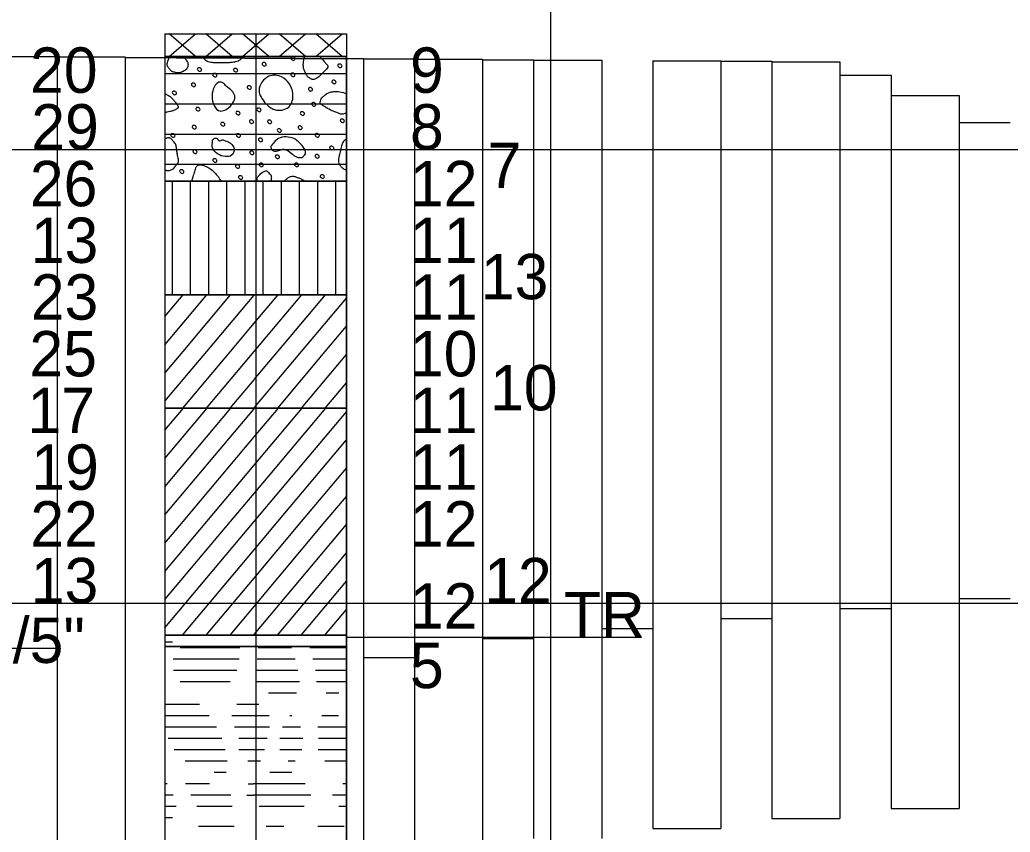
# Model space of a CAD drawing. Extents: x -2280229 to 1306, y -58886 to 440.
# Drawn here: x 461.59 to 505.23, y 72.12 to 107.93 of the extents above; entities that cross this region are included whole.
import ezdxf

# ---------------------------------------------------------------- set-up
doc = ezdxf.new("R2010")
doc.units = 0
for name, color, linetype in [('BR_P_Sub_Deep_Object', 7, 'Continuous'), ('GT_Project_Soil_Layers', 7, 'Continuous'), ('SC_Scratch2', 7, 'Continuous'), ('SC_Scratch3', 7, 'Continuous'), ('SH_Minor_Grid_Line', 7, 'Continuous')]:
    doc.layers.add(name, color=color, linetype=linetype)

msp = doc.modelspace()

# ---------------------------------------------------------------- linework, layer by layer
at = {"layer": 'BR_P_Sub_Deep_Object'}
for p, q in [((463.234, 106.302), (463.234, 70.968)), ((466.234, 106.287), (466.234, 70.968)), ((466.234, 106.268), (468.484, 106.268)), ((468.484, 106.254), (471.484, 106.254)), ((471.484, 106.234), (473.734, 106.234)), ((473.734, 106.22), (476.734, 106.22)), ((476.734, 106.22), (476.734, 70.824)), ((476.734, 106.201), (478.984, 106.201)), ((478.984, 106.201), (478.984, 71.405)), ((481.984, 106.186), (481.984, 71.405)), ((484.234, 106.167), (484.234, 71.844)), ((487.234, 106.153), (487.234, 71.844)), ((489.484, 106.134), (489.484, 72.283)), ((489.484, 106.119), (492.484, 106.119)), ((492.484, 106.119), (492.484, 72.283)), ((492.484, 106.1), (494.734, 106.1)), ((494.734, 106.1), (494.734, 72.722)), ((494.734, 106.076), (497.734, 106.076)), ((497.734, 106.076), (497.734, 72.722)), ((497.734, 105.481), (499.984, 105.481)), ((499.984, 105.481), (499.984, 73.161)), ((499.984, 104.588), (502.984, 104.588)), ((502.984, 104.588), (502.984, 73.161)), ((502.984, 103.398), (505.234, 103.398)), ((502.984, 82.412), (505.234, 82.412)), ((497.734, 81.973), (499.984, 81.973)), ((492.484, 81.534), (494.734, 81.534)), ((487.234, 81.095), (489.484, 81.095)), ((481.984, 80.656), (484.234, 80.656)), ((463.234, 80.221), (460.984, 80.221)), ((476.734, 79.824), (478.984, 79.824)), ((499.984, 73.161), (502.984, 73.161)), ((494.734, 72.722), (497.734, 72.722)), ((489.484, 72.283), (492.484, 72.283))]:
    msp.add_line(p, q, dxfattribs=at)
at = {"layer": 'GT_Project_Soil_Layers'}
for p, q in [((468.172, 106.308), (469.326, 107.308)), ((469.326, 106.308), (468.172, 107.308)), ((469.788, 106.308), (470.943, 107.308)), ((470.943, 106.308), (469.788, 107.308)), ((471.405, 106.308), (472.56, 107.308)), ((472.56, 106.308), (471.405, 107.308)), ((473.021, 106.308), (474.176, 107.308)), ((474.176, 106.308), (473.021, 107.308)), ((474.638, 106.308), (475.793, 107.308)), ((475.793, 106.308), (474.638, 107.308)), ((467.982, 106.308), (467.982, 106.308)), ((467.984, 105.558), (471.913, 105.558)), ((471.916, 105.558), (475.984, 105.558)), ((467.984, 104.225), (471.913, 104.225)), ((471.916, 104.225), (475.984, 104.225)), ((467.984, 102.891), (471.913, 102.891)), ((471.916, 102.891), (475.984, 102.891)), ((467.984, 101.557), (471.913, 101.557)), ((471.916, 101.557), (475.984, 101.557)), ((468.316, 98.309), (468.316, 100.808)), ((469.116, 98.309), (469.116, 100.808)), ((469.916, 98.309), (469.916, 100.808)), ((470.716, 98.309), (470.716, 100.808)), ((471.516, 98.309), (471.516, 100.808)), ((472.316, 98.309), (472.316, 100.808)), ((473.116, 98.309), (473.116, 100.808)), ((473.916, 98.309), (473.916, 100.808)), ((474.716, 98.309), (474.716, 100.808)), ((475.516, 98.309), (475.516, 100.808)), ((468.316, 95.808), (468.316, 98.309)), ((469.116, 95.808), (469.116, 98.309)), ((469.916, 95.808), (469.916, 98.309)), ((470.716, 95.808), (470.716, 98.309)), ((471.516, 95.808), (471.516, 98.309)), ((472.316, 95.808), (472.316, 98.309)), ((473.116, 95.808), (473.116, 98.309)), ((473.916, 95.808), (473.916, 98.309)), ((474.716, 95.808), (474.716, 98.309)), ((475.516, 95.808), (475.516, 98.309)), ((467.984, 94.846), (468.792, 95.808)), ((467.984, 93.601), (469.836, 95.808)), ((468.783, 93.309), (470.881, 95.808)), ((469.827, 93.309), (471.913, 95.794)), ((471.916, 95.794), (471.928, 95.808)), ((471.916, 94.549), (472.973, 95.808)), ((471.919, 93.309), (474.017, 95.808)), ((472.964, 93.309), (475.062, 95.808)), ((474.008, 93.309), (475.984, 95.662)), ((470.872, 93.309), (471.913, 94.549)), ((475.053, 93.309), (475.984, 94.418)), ((467.984, 92.356), (468.783, 93.309)), ((467.984, 91.112), (469.827, 93.309)), ((468.773, 90.808), (470.872, 93.309)), ((469.818, 90.808), (471.916, 93.309)), ((471.919, 90.819), (474.009, 93.309)), ((471.919, 92.064), (472.964, 93.309)), ((472.954, 90.808), (475.053, 93.309)), ((473.999, 90.808), (475.984, 93.173)), ((470.862, 90.808), (471.913, 92.06)), ((475.043, 90.808), (475.984, 91.929)), ((467.984, 89.834), (468.801, 90.808)), ((467.984, 88.59), (469.846, 90.808)), ((467.984, 87.346), (470.89, 90.808)), ((471.906, 90.808), (471.913, 90.816)), ((471.916, 90.782), (471.938, 90.808)), ((471.916, 89.538), (472.982, 90.808)), ((471.916, 88.294), (474.027, 90.808)), ((471.916, 87.049), (475.071, 90.808)), ((467.984, 86.101), (471.913, 90.782)), ((471.919, 85.809), (475.984, 90.651)), ((468.783, 85.809), (471.913, 89.538)), ((472.964, 85.809), (475.984, 89.407)), ((469.827, 85.809), (471.913, 88.294)), ((474.008, 85.809), (475.984, 88.162)), ((470.872, 85.809), (471.913, 87.049)), ((475.053, 85.809), (475.984, 86.918)), ((467.984, 84.856), (468.783, 85.809)), ((467.984, 83.612), (469.827, 85.809)), ((467.984, 82.368), (470.872, 85.809)), ((467.984, 81.123), (471.916, 85.809)), ((471.916, 82.072), (475.053, 85.809)), ((471.916, 80.827), (475.984, 85.673)), ((471.919, 83.319), (474.009, 85.809)), ((471.919, 84.564), (472.964, 85.809)), ((468.764, 80.808), (471.913, 84.56)), ((472.945, 80.808), (475.984, 84.429)), ((469.808, 80.808), (471.913, 83.316)), ((473.989, 80.808), (475.984, 83.184)), ((470.853, 80.808), (471.913, 82.071)), ((475.034, 80.808), (475.984, 81.94)), ((471.897, 80.808), (471.913, 80.827)), ((468.32, 80.493), (467.984, 80.493)), ((471.28, 80.243), (468.663, 80.243)), ((473.562, 80.243), (472.097, 80.243)), ((475.984, 80.243), (474.366, 80.243)), ((471.263, 79.743), (468.352, 79.743)), ((473.717, 79.743), (472.048, 79.743)), ((475.984, 79.743), (474.501, 79.743)), ((471.159, 79.243), (468.369, 79.243)), ((473.845, 79.243), (471.986, 79.243)), ((475.984, 79.243), (474.615, 79.243)), ((470.864, 78.743), (468.657, 78.743)), ((473.92, 78.743), (471.993, 78.743)), ((475.984, 78.743), (474.658, 78.743)), ((473.781, 78.243), (472.551, 78.243)), ((475.655, 78.243), (475.096, 78.243)), ((469.514, 77.743), (468.027, 77.743)), ((471.882, 77.743), (471.159, 77.743)), ((472.121, 77.743), (471.882, 77.743)), ((469.934, 77.243), (467.984, 77.243)), ((471.882, 77.243), (470.927, 77.243)), ((472.584, 77.243), (471.882, 77.243)), ((473.581, 77.243), (473.488, 77.243)), ((475.638, 77.243), (474.902, 77.243)), ((470.26, 76.743), (467.984, 76.743)), ((471.882, 76.743), (471.052, 76.743)), ((472.592, 76.743), (471.882, 76.743)), ((473.955, 76.743), (473.167, 76.743)), ((475.96, 76.743), (474.724, 76.743)), ((470.491, 76.243), (468.121, 76.243)), ((471.882, 76.243), (471.245, 76.243)), ((472.484, 76.243), (471.882, 76.243)), ((474.057, 76.243), (473.041, 76.243)), ((475.984, 76.243), (474.752, 76.243)), ((470.646, 75.743), (468.386, 75.743)), ((471.882, 75.743), (471.248, 75.743)), ((472.374, 75.743), (471.882, 75.743)), ((474.019, 75.743), (473.053, 75.743)), ((475.984, 75.743), (474.735, 75.743)), ((470.732, 75.243), (468.873, 75.243)), ((471.882, 75.243), (471.635, 75.243)), ((472.195, 75.243), (471.882, 75.243)), ((473.72, 75.243), (473.42, 75.243)), ((475.984, 75.243), (475.034, 75.243)), ((470.683, 74.743), (470.158, 74.743)), ((473.57, 74.743), (472.609, 74.743)), ((468.085, 74.243), (467.984, 74.243)), ((469.953, 74.243), (468.885, 74.243)), ((471.655, 74.243), (471.882, 74.243)), ((474.16, 74.243), (471.882, 74.243)), ((475.984, 74.243), (475.824, 74.243)), ((468.341, 73.743), (467.984, 73.743)), ((470.893, 73.743), (469.127, 73.743)), ((471.591, 73.743), (471.882, 73.743)), ((474.42, 73.743), (471.882, 73.743)), ((475.984, 73.743), (475.376, 73.743)), ((468.476, 73.243), (467.984, 73.243)), ((470.954, 73.243), (469.383, 73.243)), ((474.125, 73.243), (472.132, 73.243)), ((475.984, 73.243), (475.65, 73.243)), ((468.32, 72.743), (467.984, 72.743)), ((471.029, 72.375), (469.46, 72.375)), ((473.228, 72.375), (472.453, 72.375)), ((475.876, 72.375), (474.723, 72.375))]:
    msp.add_line(p, q, dxfattribs=at)
for points in [[(475.984, 106.308), (467.984, 106.308), (467.984, 100.808), (475.984, 100.808)], [(467.984, 95.808), (475.984, 95.808), (475.984, 100.808), (467.984, 100.808)], [(475.984, 95.808), (467.984, 95.808), (467.984, 90.808), (475.984, 90.808)], [(475.984, 90.808), (467.984, 90.808), (467.984, 80.808), (475.984, 80.808)], [(467.984, 80.308), (475.984, 80.308), (475.984, 80.808), (467.984, 80.808)], [(467.984, 65.308), (475.984, 65.308), (475.984, 80.308), (467.984, 80.308)]]:
    msp.add_lwpolyline(points, close=True, dxfattribs=at)
for points in [[(468.174, 106.308), (468.144, 106.218), (468.113, 106.128), (468.082, 106.039), (468.045, 105.933), (468.121, 105.831), (468.212, 105.73), (468.276, 105.658), (468.346, 105.633), (468.422, 105.617), (468.541, 105.591), (468.674, 105.604), (468.795, 105.665), (468.879, 105.708), (468.948, 105.765), (468.988, 105.844), (469.029, 105.922), (469.005, 106.028), (468.957, 106.104), (468.91, 106.177), (468.861, 106.248), (468.8, 106.308)], [(471.388, 106.308), (471.393, 106.278), (471.389, 106.251), (471.373, 106.234), (471.313, 106.167), (471.204, 106.094), (471.098, 106.074), (470.907, 106.037), (470.716, 106.031), (470.525, 106.027), (470.35, 106.024), (470.174, 106.027), (469.998, 106.05), (469.886, 106.065), (469.786, 106.138), (469.702, 106.21), (469.678, 106.23), (469.667, 106.268), (469.666, 106.308)], [(474.8, 106.308), (474.896, 106.204), (474.992, 106.099), (475.088, 105.995), (475.219, 105.853), (474.99, 105.634), (474.828, 105.477), (474.696, 105.349), (474.498, 105.264), (474.375, 105.347), (474.278, 105.411), (474.196, 105.517), (474.148, 105.639), (474.087, 105.794), (474.078, 105.955), (474.1, 106.109), (474.109, 106.177), (474.123, 106.243), (474.147, 106.308)], [(475.308, 103.932), (475.179, 104.007), (475.049, 104.083), (474.92, 104.159), (474.802, 104.227), (474.865, 104.464), (474.983, 104.564), (475.122, 104.68), (475.267, 104.747), (475.421, 104.759), (475.605, 104.772), (475.799, 104.746), (475.984, 104.668)], [(467.984, 104.667), (468.011, 104.655), (468.038, 104.642), (468.065, 104.629), (468.223, 104.547), (468.329, 104.434), (468.438, 104.304), (468.508, 104.221), (468.595, 104.051), (468.503, 103.997), (468.369, 103.916), (468.217, 103.887), (468.065, 103.85), (468.038, 103.844), (468.011, 103.835), (467.984, 103.826)], [(475.984, 103.825), (475.886, 103.791), (475.788, 103.751), (475.696, 103.785), (475.567, 103.834), (475.437, 103.883), (475.308, 103.932)], [(467.984, 101.301), (468.009, 101.294), (468.034, 101.29), (468.058, 101.288), (468.185, 101.277), (468.328, 101.332), (468.448, 101.471), (468.623, 101.672), (468.545, 101.888), (468.517, 102.089), (468.494, 102.254), (468.482, 102.414), (468.357, 102.571), (468.276, 102.673), (468.147, 102.744), (468.058, 102.709), (468.035, 102.7), (468.009, 102.687), (467.984, 102.671)], [(475.984, 102.669), (475.913, 102.624), (475.843, 102.557), (475.81, 102.479), (475.793, 102.441), (475.78, 102.403), (475.765, 102.364)], [(475.765, 102.364), (475.727, 102.197), (475.688, 102.029), (475.65, 101.861), (475.62, 101.731), (475.632, 101.601), (475.741, 101.471), (475.818, 101.38), (475.901, 101.327), (475.984, 101.302)], [(469.167, 100.808), (469.218, 100.981), (469.27, 101.155), (469.322, 101.328), (469.407, 101.612), (469.968, 101.414), (470.197, 101.166), (470.299, 101.056), (470.401, 100.929), (470.442, 100.808)], [(472.226, 101.171), (472.28, 101.198), (472.333, 101.224), (472.386, 101.251), (472.451, 101.283), (472.517, 101.225), (472.581, 101.159), (472.652, 101.088), (472.675, 101.015), (472.673, 100.941), (472.672, 100.897), (472.662, 100.852), (472.643, 100.808)], [(472.054, 100.808), (472.055, 100.814), (472.055, 100.82), (472.055, 100.826), (472.054, 100.88), (472.031, 100.947), (472.066, 100.988), (472.12, 101.049), (472.173, 101.11), (472.226, 101.171)], [(473.263, 100.808), (473.294, 100.861), (473.334, 100.909), (473.393, 100.948), (473.515, 101.029), (473.661, 101.037), (473.781, 100.993), (473.92, 100.941), (474.058, 100.878), (474.195, 100.809), (474.196, 100.809), (474.197, 100.809), (474.198, 100.808)]]:
    msp.add_open_spline(points, degree=3, dxfattribs=at)
for points in [[(473.7, 106.25), (473.72, 106.21), (473.696, 106.162), (473.641, 106.139), (473.59, 106.157), (473.55, 106.194), (473.533, 106.234), (473.565, 106.289), (473.613, 106.294), (473.653, 106.29), (473.7, 106.25)], [(469.58, 105.767), (469.597, 105.73), (469.575, 105.682), (469.52, 105.659), (469.468, 105.675), (469.428, 105.712), (469.412, 105.754), (469.443, 105.807), (469.492, 105.814), (469.532, 105.81), (469.58, 105.767)], [(471.176, 105.735), (471.194, 105.697), (471.171, 105.649), (471.116, 105.625), (471.064, 105.644), (471.024, 105.68), (471.008, 105.72), (471.039, 105.775), (471.088, 105.78), (471.128, 105.777), (471.176, 105.735)], [(472.43, 105.997), (472.45, 105.957), (472.426, 105.909), (472.373, 105.885), (472.321, 105.902), (472.281, 105.94), (472.265, 105.98), (472.295, 106.034), (472.345, 106.04), (472.385, 106.037), (472.43, 105.997)], [(475.77, 105.929), (475.786, 105.892), (475.763, 105.844), (475.71, 105.82), (475.658, 105.837), (475.618, 105.875), (475.6, 105.915), (475.631, 105.969), (475.68, 105.975), (475.72, 105.972), (475.77, 105.929)], [(470.688, 104.994), (471.06, 104.574), (470.802, 104.054), (470.348, 103.925), (470.122, 104.217), (470.073, 104.687), (470.202, 105.044), (470.365, 105.172), (470.558, 105.14), (470.688, 104.994)], [(470.259, 105.513), (470.276, 105.476), (470.253, 105.428), (470.199, 105.405), (470.148, 105.421), (470.108, 105.458), (470.089, 105.498), (470.121, 105.553), (470.169, 105.56), (470.209, 105.556), (470.259, 105.513)], [(472.408, 104.242), (472.133, 104.815), (472.568, 105.434), (473.118, 105.41), (473.621, 104.677), (473.438, 104.082), (472.82, 103.967), (472.408, 104.242)], [(473.693, 105.535), (473.713, 105.495), (473.69, 105.445), (473.636, 105.424), (473.585, 105.44), (473.545, 105.477), (473.526, 105.517), (473.558, 105.572), (473.608, 105.577), (473.648, 105.575), (473.693, 105.535)], [(475.51, 105.215), (475.526, 105.179), (475.505, 105.13), (475.45, 105.107), (475.398, 105.125), (475.358, 105.162), (475.341, 105.202), (475.373, 105.257), (475.421, 105.262), (475.461, 105.259), (475.51, 105.215)], [(468.477, 104.732), (468.497, 104.692), (468.473, 104.644), (468.418, 104.62), (468.367, 104.639), (468.327, 104.675), (468.31, 104.715), (468.342, 104.77), (468.39, 104.775), (468.43, 104.772), (468.477, 104.732)], [(469.322, 105.087), (469.338, 105.049), (469.315, 105), (469.26, 104.977), (469.208, 104.995), (469.168, 105.032), (469.152, 105.072), (469.183, 105.127), (469.232, 105.132), (469.272, 105.129), (469.322, 105.087)], [(471.778, 104.972), (471.794, 104.934), (471.771, 104.885), (471.718, 104.862), (471.666, 104.88), (471.626, 104.917), (471.608, 104.957), (471.639, 105.012), (471.688, 105.017), (471.728, 105.014), (471.778, 104.972)], [(474.471, 104.895), (474.491, 104.855), (474.468, 104.805), (474.413, 104.784), (474.361, 104.8), (474.321, 104.837), (474.305, 104.877), (474.336, 104.932), (474.385, 104.937), (474.425, 104.935), (474.471, 104.895)], [(469.515, 104.017), (469.532, 103.979), (469.51, 103.93), (469.455, 103.909), (469.403, 103.925), (469.363, 103.962), (469.347, 104.002), (469.378, 104.057), (469.427, 104.062), (469.467, 104.06), (469.515, 104.017)], [(471.278, 103.842), (471.298, 103.8), (471.275, 103.752), (471.22, 103.73), (471.17, 103.747), (471.128, 103.784), (471.112, 103.824), (471.143, 103.879), (471.192, 103.884), (471.232, 103.882), (471.278, 103.842)], [(472.206, 103.984), (472.223, 103.947), (472.2, 103.899), (472.146, 103.875), (472.095, 103.892), (472.055, 103.93), (472.036, 103.97), (472.068, 104.024), (472.118, 104.03), (472.158, 104.027), (472.206, 103.984)], [(474.616, 104.23), (474.636, 104.19), (474.613, 104.142), (474.56, 104.119), (474.508, 104.135), (474.468, 104.174), (474.45, 104.214), (474.481, 104.267), (474.531, 104.274), (474.571, 104.27), (474.616, 104.23)], [(471.876, 103.465), (471.895, 103.429), (471.871, 103.38), (471.816, 103.357), (471.765, 103.374), (471.725, 103.412), (471.708, 103.452), (471.74, 103.505), (471.788, 103.512), (471.828, 103.509), (471.876, 103.465)], [(472.673, 103.463), (472.693, 103.423), (472.67, 103.375), (472.615, 103.352), (472.563, 103.37), (472.523, 103.407), (472.506, 103.447), (472.538, 103.502), (472.586, 103.507), (472.626, 103.503), (472.673, 103.463)], [(474.116, 103.822), (474.135, 103.785), (474.111, 103.737), (474.056, 103.714), (474.005, 103.732), (473.965, 103.769), (473.948, 103.809), (473.98, 103.864), (474.028, 103.869), (474.068, 103.865), (474.116, 103.822)], [(475.878, 103.506), (475.894, 103.468), (475.871, 103.42), (475.818, 103.398), (475.766, 103.415), (475.726, 103.451), (475.709, 103.491), (475.739, 103.546), (475.789, 103.551), (475.829, 103.55), (475.878, 103.506)], [(469.353, 103.227), (469.37, 103.189), (469.348, 103.14), (469.293, 103.117), (469.242, 103.135), (469.202, 103.172), (469.185, 103.212), (469.215, 103.267), (469.265, 103.272), (469.305, 103.269), (469.353, 103.227)], [(470.61, 103.352), (470.626, 103.315), (470.603, 103.267), (470.55, 103.243), (470.498, 103.26), (470.458, 103.298), (470.44, 103.338), (470.471, 103.392), (470.52, 103.398), (470.56, 103.395), (470.61, 103.352)], [(473.103, 103.072), (473.119, 103.034), (473.098, 102.986), (473.043, 102.962), (472.991, 102.981), (472.951, 103.017), (472.934, 103.057), (472.966, 103.112), (473.014, 103.117), (473.054, 103.114), (473.103, 103.072)], [(474.017, 103.204), (474.037, 103.164), (474.014, 103.116), (473.959, 103.093), (473.907, 103.109), (473.867, 103.148), (473.85, 103.188), (473.882, 103.241), (473.93, 103.248), (473.97, 103.244), (474.017, 103.204)], [(468.413, 102.856), (468.432, 102.818), (468.408, 102.769), (468.353, 102.746), (468.302, 102.764), (468.262, 102.801), (468.245, 102.841), (468.277, 102.896), (468.325, 102.901), (468.365, 102.898), (468.413, 102.856)], [(470.087, 102.631), (470.098, 102.241), (470.303, 102.013), (470.647, 101.898), (470.922, 101.954), (471.037, 102.229), (470.877, 102.483), (470.647, 102.596), (470.51, 102.631), (470.383, 102.584), (470.282, 102.688), (470.155, 102.699), (470.087, 102.631)], [(471.297, 102.856), (471.313, 102.818), (471.292, 102.769), (471.237, 102.746), (471.185, 102.764), (471.145, 102.801), (471.128, 102.841), (471.16, 102.896), (471.208, 102.901), (471.248, 102.898), (471.297, 102.856)], [(472.271, 102.661), (472.288, 102.624), (472.264, 102.574), (472.211, 102.553), (472.159, 102.569), (472.119, 102.606), (472.103, 102.646), (472.133, 102.701), (472.183, 102.706), (472.223, 102.704), (472.271, 102.661)], [(472.651, 102.349), (472.991, 102.689), (473.671, 102.689), (474.028, 102.381), (474.175, 102.024), (474.011, 101.863), (473.671, 101.944), (473.413, 102.154), (473.186, 102.219), (472.813, 102.138), (472.685, 102.219), (472.651, 102.349)], [(474.773, 102.863), (474.79, 102.825), (474.767, 102.777), (474.713, 102.753), (474.662, 102.772), (474.622, 102.808), (474.603, 102.848), (474.635, 102.903), (474.683, 102.908), (474.723, 102.905), (474.773, 102.863)], [(469.385, 102.143), (469.403, 102.104), (469.38, 102.056), (469.325, 102.034), (469.273, 102.051), (469.233, 102.088), (469.217, 102.128), (469.248, 102.183), (469.297, 102.188), (469.337, 102.186), (469.385, 102.143)], [(471.892, 102.096), (471.909, 102.059), (471.885, 102.009), (471.832, 101.987), (471.78, 102.004), (471.74, 102.041), (471.722, 102.081), (471.754, 102.136), (471.802, 102.141), (471.844, 102.139), (471.892, 102.096)], [(475.413, 102.304), (475.43, 102.268), (475.406, 102.218), (475.353, 102.196), (475.301, 102.213), (475.261, 102.249), (475.243, 102.289), (475.275, 102.344), (475.325, 102.349), (475.365, 102.348), (475.413, 102.304)], [(470.26, 101.753), (470.277, 101.716), (470.255, 101.668), (470.2, 101.644), (470.148, 101.661), (470.108, 101.699), (470.092, 101.739), (470.123, 101.793), (470.172, 101.799), (470.212, 101.796), (470.26, 101.753)], [(473.013, 101.918), (473.033, 101.878), (473.01, 101.829), (472.956, 101.806), (472.905, 101.824), (472.865, 101.861), (472.846, 101.901), (472.878, 101.956), (472.926, 101.961), (472.968, 101.958), (473.013, 101.918)], [(474.771, 101.938), (474.788, 101.901), (474.765, 101.851), (474.711, 101.83), (474.66, 101.846), (474.62, 101.883), (474.601, 101.923), (474.633, 101.978), (474.681, 101.983), (474.723, 101.981), (474.771, 101.938)], [(468.803, 101.268), (468.82, 101.229), (468.797, 101.181), (468.742, 101.158), (468.692, 101.176), (468.65, 101.213), (468.633, 101.253), (468.665, 101.308), (468.713, 101.313), (468.753, 101.309), (468.803, 101.268)], [(471.265, 101.494), (471.282, 101.456), (471.258, 101.408), (471.203, 101.386), (471.153, 101.403), (471.112, 101.439), (471.095, 101.479), (471.127, 101.534), (471.175, 101.539), (471.215, 101.538), (471.265, 101.494)], [(472.303, 101.559), (472.32, 101.521), (472.298, 101.473), (472.243, 101.449), (472.191, 101.468), (472.151, 101.504), (472.135, 101.544), (472.166, 101.599), (472.215, 101.604), (472.255, 101.601), (472.303, 101.559)], [(473.858, 101.559), (473.875, 101.521), (473.853, 101.473), (473.798, 101.449), (473.746, 101.468), (473.706, 101.504), (473.69, 101.544), (473.721, 101.599), (473.77, 101.604), (473.81, 101.601), (473.858, 101.559)], [(471.393, 101.008), (471.412, 100.971), (471.388, 100.923), (471.333, 100.899), (471.282, 100.916), (471.242, 100.953), (471.225, 100.993), (471.257, 101.048), (471.305, 101.054), (471.345, 101.051), (471.393, 101.008)], [(474.995, 101.044), (475.013, 101.008), (474.99, 100.959), (474.935, 100.936), (474.883, 100.953), (474.843, 100.991), (474.826, 101.031), (474.858, 101.084), (474.906, 101.091), (474.946, 101.088), (474.995, 101.044)]]:
    msp.add_spline(points, degree=3, dxfattribs=at)
at = {"layer": 'SC_Scratch2'}
for p, q in [((467.984, 107.308), (475.984, 107.308)), ((467.984, 107.308), (467.984, 65.308)), ((471.984, 107.308), (471.984, 65.308)), ((475.984, 107.308), (475.984, 65.308)), ((460.984, 106.302), (463.234, 106.302)), ((463.234, 106.287), (466.234, 106.287)), ((467.984, 106.308), (475.984, 106.308)), ((478.984, 106.186), (481.984, 106.186)), ((481.984, 106.167), (484.234, 106.167)), ((484.234, 106.153), (487.234, 106.153)), ((467.984, 100.808), (475.984, 100.808)), ((467.984, 95.808), (475.984, 95.808)), ((467.984, 90.808), (475.984, 90.808)), ((467.984, 80.808), (475.984, 80.808)), ((467.984, 80.308), (475.984, 80.308))]:
    msp.add_line(p, q, dxfattribs=at)
at = {"layer": 'SC_Scratch3'}
msp.add_line((475.984, 80.708), (488.984, 80.708), dxfattribs=at)
at = {"layer": 'SH_Minor_Grid_Line'}
for p, q in [((484.984, 21.221), (484.984, 162.208)), ((45.429, 102.208), (603.007, 102.208)), ((45.429, 82.208), (603.007, 82.208))]:
    msp.add_line(p, q, dxfattribs=at)

# ---------------------------------------------------------------- texts
at = {"layer": 'SC_Scratch2'}
for s, p in [('20', (462.041, 104.708)), ('9', (478.784, 104.708)), ('29', (462.096, 102.208)), ('8', (478.784, 102.208)), ('7', (482.208, 100.508)), ('26', (462.032, 99.708)), ('12', (478.784, 99.708)), ('13', (462.073, 97.208)), ('11', (478.784, 97.208)), ('13', (481.905, 95.608)), ('23', (462.073, 94.708)), ('11', (478.784, 94.708)), ('25', (462.013, 92.208)), ('10', (478.784, 92.208)), ('10', (482.312, 90.708)), ('17', (461.924, 89.708)), ('11', (478.784, 89.708)), ('19', (462.096, 87.208)), ('11', (478.784, 87.208)), ('22', (462.054, 84.708)), ('12', (478.784, 84.708)), ('13', (462.073, 82.208)), ('12', (482.055, 82.208)), ('12', (478.784, 81.089)), ('TR', (485.57, 80.708)), ('19/50/5"', (454.587, 79.577)), ('5', (478.784, 78.466))]:
    msp.add_text(s, height=2, dxfattribs=at).set_placement(p)

doc.saveas('drawing.dxf')
